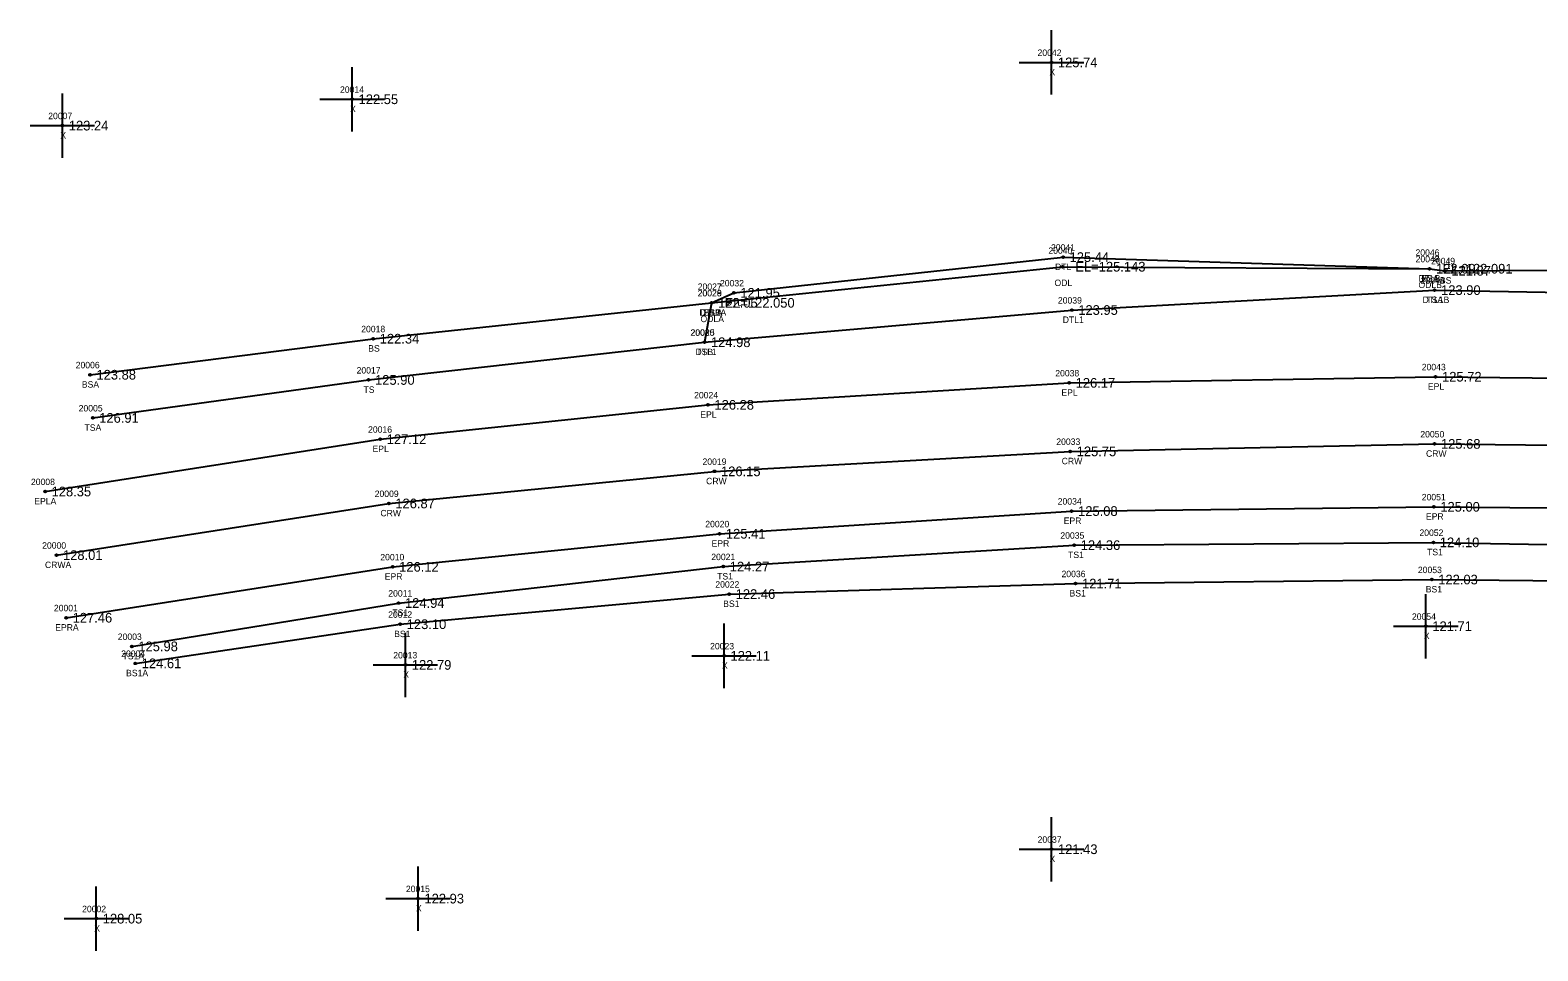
# Model space of a CAD drawing. Extents: x 2375812 to 2377225, y 1024470 to 1025135.
# Drawn here: x 2375812.4 to 2376046.3, y 1024854.8 to 1024997.6 of the extents above; entities that cross this region are included whole.
import ezdxf

# ---------------------------------------------------------------- set-up
doc = ezdxf.new("R2010")
doc.units = 0
for name, color, linetype in [('RD_DTM_BkLn1', 7, 'Continuous'), ('RD_DTM_BkLn2', 7, 'Continuous'), ('RD_DTM_BkLn_txCode', 7, 'Continuous'), ('RD_EX_H2O', 7, 'Continuous'), ('RD_EX_H2O_txCode', 7, 'Continuous'), ('RD_EX_Misc', 7, 'Continuous'), ('RD_EX_Misc_txCode', 7, 'Continuous'), ('RD_EX_Road', 7, 'Continuous'), ('RD_EX_Road_txCode', 7, 'Continuous'), ('RD_EX_TX_H2O_ELEV', 7, 'Continuous'), ('RD_EX_TX_Misc_ELEV', 7, 'Continuous'), ('RD_EX_TX_Road_ELEV', 7, 'Continuous'), ('RD_HC_Survey_ELEV', 7, 'Continuous'), ('RD_HC_Survey_txCode', 7, 'Continuous'), ('RD_SMD_Locator', 7, 'Continuous')]:
    doc.layers.add(name, color=color, linetype=linetype)

msp = doc.modelspace()

# ---------------------------------------------------------------- linework, layer by layer
at = {"layer": 'RD_DTM_BkLn1'}
msp.add_lwpolyline([(2375816.52, 1024916.17), (2375868.08, 1024924.19), (2375918.61, 1024929.17), (2375973.79, 1024932.27), (2376030.31, 1024933.43), (2376124.39, 1024932.38), (2376221.5, 1024931.17), (2376315.07, 1024930.06), (2376410.07, 1024928.46), (2376471.65, 1024927.66)], dxfattribs=at)
at = {"layer": 'RD_DTM_BkLn2'}
for points in [[(2376029.54, 1024960.61), (2376031.93, 1024960.3), (2376124.75, 1024960.87), (2376220.58, 1024959.2), (2376313.51, 1024957.48), (2376410.53, 1024957.56), (2376415.87, 1024960.14)], [(2376030.33, 1024957.29), (2376124.82, 1024955.55), (2376220.6, 1024953.97), (2376313.35, 1024951.76), (2376409.92, 1024949.91), (2376424.84, 1024950.05)], [(2375821.71, 1024944.16), (2375865.66, 1024949.75), (2375918.16, 1024955.32)], [(2375822.14, 1024937.46), (2375864.94, 1024943.35), (2375917.05, 1024949.2)], [(2375828.21, 1024902.01), (2375869.58, 1024908.74), (2375919.97, 1024914.39), (2375974.42, 1024917.72), (2376030.13, 1024918.15), (2376124.55, 1024916.47), (2376157.47, 1024915.82), (2376169.1, 1024907.28), (2376220.97, 1024905.03), (2376312.67, 1024905.48), (2376408.92, 1024907.12), (2376437.56, 1024903.89), (2376467.32, 1024909.88), (2376471.6, 1024914.56)], [(2375828.74, 1024899.38), (2375869.85, 1024905.45), (2375920.89, 1024910.13), (2375974.62, 1024911.75), (2376029.89, 1024912.38), (2376123.86, 1024911.48), (2376128.27, 1024903.93), (2376220.97, 1024899.73), (2376312.35, 1024901.44), (2376410.93, 1024898.57), (2376439.29, 1024896.5), (2376469.35, 1024899.44), (2376491.09, 1024911.59)]]:
    msp.add_lwpolyline(points, dxfattribs=at)
at = {"layer": 'RD_EX_H2O'}
for points in [[(2375918.16, 1024955.32), (2375921.61, 1024956.87), (2375972.69, 1024962.41), (2376029.54, 1024960.61)], [(2375918.16, 1024955.32), (2375972.59, 1024960.92), (2376029.54, 1024960.61)], [(2375918.16, 1024955.32), (2375917.05, 1024949.2), (2375974.04, 1024954.2), (2376030.33, 1024957.29)]]:
    msp.add_lwpolyline(points, dxfattribs=at)
at = {"layer": 'RD_EX_Misc'}
for p, q in [((2375970.88, 1024987.62), (2375970.88, 1024997.62)), ((2375862.38, 1024981.9), (2375862.38, 1024991.9)), ((2375965.88, 1024992.62), (2375975.88, 1024992.62)), ((2375817.42, 1024977.81), (2375817.42, 1024987.81)), ((2375857.38, 1024986.9), (2375867.38, 1024986.9)), ((2375812.42, 1024982.81), (2375822.42, 1024982.81)), ((2376028.97, 1024900.14), (2376028.97, 1024910.14)), ((2375920.08, 1024895.55), (2375920.08, 1024905.55)), ((2376023.97, 1024905.14), (2376033.97, 1024905.14)), ((2375870.64, 1024894.14), (2375870.64, 1024904.14)), ((2375915.08, 1024900.55), (2375925.08, 1024900.55)), ((2375865.64, 1024899.14), (2375875.64, 1024899.14)), ((2375970.89, 1024865.54), (2375970.89, 1024875.54)), ((2375965.89, 1024870.54), (2375975.89, 1024870.54)), ((2375872.6, 1024857.88), (2375872.6, 1024867.88)), ((2375822.69, 1024854.77), (2375822.69, 1024864.77)), ((2375867.6, 1024862.88), (2375877.6, 1024862.88)), ((2375817.69, 1024859.77), (2375827.69, 1024859.77))]:
    msp.add_line(p, q, dxfattribs=at)
at = {"layer": 'RD_EX_Road'}
for points in [[(2375814.75, 1024926.04), (2375866.75, 1024934.16), (2375917.59, 1024939.49), (2375973.63, 1024942.9), (2376030.48, 1024943.85), (2376125.42, 1024942.84), (2376221.25, 1024941.27), (2376314.97, 1024940.08), (2376410.64, 1024938.26), (2376471.87, 1024938.44)], [(2375818.02, 1024906.46), (2375868.67, 1024914.36), (2375919.37, 1024919.49), (2375974.01, 1024923.01), (2376030.21, 1024923.67), (2376124.55, 1024922.83), (2376221.09, 1024921.25), (2376314, 1024920.33), (2376408.92, 1024919.22), (2376471.42, 1024917.38)]]:
    msp.add_lwpolyline(points, dxfattribs=at)
at = {"layer": 'RD_SMD_Locator'}
for centre in [(2375970.88, 1024992.62), (2375862.38, 1024986.9), (2375817.42, 1024982.81), (2375972.59, 1024960.92), (2375972.69, 1024962.41), (2376029.54, 1024960.61), (2376029.54, 1024960.61), (2376029.54, 1024960.61), (2376031.93, 1024960.3), (2375921.61, 1024956.87), (2376030.33, 1024957.29), (2376030.33, 1024957.29), (2375918.16, 1024955.32), (2375918.16, 1024955.32), (2375918.16, 1024955.32), (2375918.16, 1024955.32), (2375974.04, 1024954.2), (2375865.66, 1024949.75), (2375917.05, 1024949.2), (2375917.05, 1024949.2), (2375821.71, 1024944.16), (2375864.94, 1024943.35), (2375973.63, 1024942.9), (2376030.48, 1024943.85), (2375822.14, 1024937.46), (2375917.59, 1024939.49), (2375866.75, 1024934.16), (2376030.31, 1024933.43), (2375973.79, 1024932.27), (2375918.61, 1024929.17), (2375814.75, 1024926.04), (2375868.08, 1024924.19), (2376030.21, 1024923.67), (2375974.01, 1024923.01), (2375919.37, 1024919.49), (2375974.42, 1024917.72), (2376030.13, 1024918.15), (2375816.52, 1024916.17), (2375868.67, 1024914.36), (2375919.97, 1024914.39), (2375974.62, 1024911.75), (2376029.89, 1024912.38), (2375920.89, 1024910.13), (2375869.58, 1024908.74), (2375818.02, 1024906.46), (2375869.85, 1024905.45), (2376028.97, 1024905.14), (2375828.21, 1024902.01), (2375920.08, 1024900.55), (2375828.74, 1024899.38), (2375870.64, 1024899.14), (2375970.89, 1024870.54), (2375872.6, 1024862.88), (2375822.69, 1024859.77)]:
    msp.add_circle(centre, 0.15, dxfattribs=at)

# ---------------------------------------------------------------- texts
at = {"layer": 'RD_DTM_BkLn_txCode'}
for s, p in [('20048', (2376027.38, 1024961.61)), ('20049', (2376029.78, 1024961.3)), ('20045', (2376028.17, 1024958.29)), ('BSA', (2376028.27, 1024958.61)), ('BS', (2376031.15, 1024958.3)), ('20026', (2375915.98, 1024956.32)), ('BSB', (2375916.91, 1024953.32)), ('TSA', (2376029.04, 1024955.29)), ('20018', (2375863.79, 1024950.75)), ('20025', (2375914.9, 1024950.2)), ('BS', (2375864.88, 1024947.75)), ('TSB', (2375915.79, 1024947.2)), ('20006', (2375819.49, 1024945.16)), ('20017', (2375863.07, 1024944.35)), ('BSA', (2375820.44, 1024942.16)), ('TS', (2375864.15, 1024941.35)), ('20005', (2375819.95, 1024938.46)), ('TSA', (2375820.86, 1024935.46)), ('20035', (2375972.26, 1024918.72)), ('20052', (2376027.97, 1024919.15)), ('TS1', (2375973.46, 1024915.72)), ('TS1', (2376029.16, 1024916.15)), ('20021', (2375918.1, 1024915.39)), ('20053', (2376027.73, 1024913.38)), ('20022', (2375918.73, 1024911.13)), ('TS1', (2375919.01, 1024912.39)), ('20036', (2375972.44, 1024912.75)), ('20011', (2375867.99, 1024909.74)), ('BS1', (2375973.68, 1024909.75)), ('BS1', (2376028.95, 1024910.38)), ('20012', (2375867.97, 1024906.45)), ('TS1', (2375868.62, 1024906.74)), ('BS1', (2375919.95, 1024908.13)), ('20003', (2375826.02, 1024903.01)), ('BS1', (2375868.9, 1024903.45)), ('20004', (2375826.55, 1024900.38)), ('TS1A', (2375826.76, 1024900.01)), ('BS1A', (2375827.31, 1024897.38))]:
    msp.add_text(s, height=1, dxfattribs=at).set_placement(p)
at = {"layer": 'RD_EX_H2O_txCode'}
for s, p in [('20040', (2375970.4, 1024962.92)), ('20041', (2375970.81, 1024963.41)), ('20046', (2376027.36, 1024962.61)), ('DTL', (2375971.44, 1024960.41)), ('20047', (2376027.38, 1024961.61)), ('20032', (2375919.45, 1024957.87)), ('ODL', (2375971.35, 1024957.92)), ('DTLB', (2376027.82, 1024958.61)), ('20044', (2376028.17, 1024958.29)), ('20027', (2375916, 1024957.32)), ('20028', (2375916, 1024956.32)), ('20029', (2375916, 1024956.32)), ('ODLB', (2376027.82, 1024957.61)), ('DTL1A', (2375916.26, 1024953.32)), ('DTLA', (2375916.43, 1024953.32)), ('DTL', (2375920.36, 1024954.87)), ('20039', (2375971.88, 1024955.2)), ('DTL1B', (2376028.45, 1024955.29)), ('ODLA', (2375916.43, 1024952.32)), ('DTL1', (2375972.63, 1024952.2)), ('20030', (2375914.86, 1024950.2)), ('DTL1', (2375915.65, 1024947.2))]:
    msp.add_text(s, height=1, dxfattribs=at).set_placement(p)
at = {"layer": 'RD_EX_Misc_txCode'}
for s, p in [('20042', (2375968.72, 1024993.62)), ('X', (2375970.56, 1024990.62)), ('20014', (2375860.5, 1024987.9)), ('20007', (2375815.23, 1024983.81)), ('X', (2375862.06, 1024984.9)), ('X', (2375817.11, 1024980.81)), ('20054', (2376026.81, 1024906.14)), ('20023', (2375917.92, 1024901.55)), ('X', (2376028.65, 1024903.14)), ('20013', (2375868.76, 1024900.14)), ('X', (2375870.32, 1024897.14)), ('X', (2375919.76, 1024898.55)), ('20037', (2375968.73, 1024871.54)), ('X', (2375970.57, 1024868.54)), ('20015', (2375870.72, 1024863.88)), ('20002', (2375820.49, 1024860.77)), ('X', (2375872.28, 1024860.88)), ('X', (2375822.37, 1024857.77))]:
    msp.add_text(s, height=1, dxfattribs=at).set_placement(p)
at = {"layer": 'RD_EX_Road_txCode'}
for s, p in [('20038', (2375971.47, 1024943.9)), ('20043', (2376028.33, 1024944.85)), ('EPL', (2376029.28, 1024941.85)), ('20024', (2375915.44, 1024940.49)), ('EPL', (2375972.42, 1024940.9)), ('EPL', (2375916.39, 1024937.49)), ('20016', (2375864.85, 1024935.16)), ('EPL', (2375865.54, 1024932.16)), ('20008', (2375812.55, 1024927.04)), ('EPLA', (2375813.06, 1024924.04)), ('20034', (2375971.85, 1024924.01)), ('20051', (2376028.33, 1024924.67)), ('20020', (2375917.17, 1024920.49)), ('EPR', (2375972.78, 1024921.01)), ('EPR', (2376028.98, 1024921.67)), ('EPR', (2375918.14, 1024917.49)), ('20010', (2375866.75, 1024915.36)), ('EPR', (2375867.44, 1024912.36)), ('20001', (2375816.11, 1024907.46)), ('EPRA', (2375816.31, 1024904.46))]:
    msp.add_text(s, height=1, dxfattribs=at).set_placement(p)
at = {"layer": 'RD_EX_TX_H2O_ELEV'}
for s, p in [('125.44', (2375973.69, 1024961.66)), ('EL=125.143', (2375974.59, 1024960.17)), ('122.09', (2376030.54, 1024959.86)), ('EL=122.091', (2376031.54, 1024959.86)), ('121.95', (2375922.61, 1024956.12)), ('123.90', (2376031.33, 1024956.54)), ('122.05', (2375919.16, 1024954.57)), ('122.05', (2375919.16, 1024954.57)), ('EL=122.050', (2375920.16, 1024954.57)), ('123.95', (2375975.04, 1024953.45)), ('124.98', (2375918.05, 1024948.45))]:
    msp.add_text(s, height=1.5, dxfattribs=at).set_placement(p)
at = {"layer": 'RD_EX_TX_Misc_ELEV'}
for s, p in [('125.74', (2375971.88, 1024991.87)), ('122.55', (2375863.38, 1024986.15)), ('123.24', (2375818.42, 1024982.06)), ('122.09', (2376030.54, 1024959.86)), ('121.87', (2376032.93, 1024959.55)), ('123.90', (2376031.33, 1024956.54)), ('122.05', (2375919.16, 1024954.57)), ('122.34', (2375866.66, 1024949)), ('124.98', (2375918.05, 1024948.45)), ('123.88', (2375822.71, 1024943.41)), ('125.90', (2375865.94, 1024942.6)), ('126.91', (2375823.14, 1024936.71)), ('124.10', (2376031.13, 1024917.4)), ('124.36', (2375975.42, 1024916.97)), ('124.27', (2375920.97, 1024913.64)), ('121.71', (2375975.62, 1024911)), ('122.03', (2376030.89, 1024911.63)), ('122.46', (2375921.89, 1024909.38)), ('124.94', (2375870.58, 1024907.99)), ('123.10', (2375870.85, 1024904.7)), ('121.71', (2376029.97, 1024904.39)), ('125.98', (2375829.21, 1024901.26)), ('122.11', (2375921.08, 1024899.8)), ('124.61', (2375829.74, 1024898.63)), ('122.79', (2375871.64, 1024898.39)), ('121.43', (2375971.89, 1024869.79)), ('122.93', (2375873.6, 1024862.13)), ('128.05', (2375823.69, 1024859.02))]:
    msp.add_text(s, height=1.5, dxfattribs=at).set_placement(p)
at = {"layer": 'RD_EX_TX_Road_ELEV'}
for s, p in [('125.72', (2376031.48, 1024943.1)), ('126.17', (2375974.63, 1024942.15)), ('126.28', (2375918.59, 1024938.74)), ('127.12', (2375867.75, 1024933.41)), ('128.35', (2375815.75, 1024925.29)), ('125.08', (2375975.01, 1024922.26)), ('125.00', (2376031.21, 1024922.92)), ('125.41', (2375920.37, 1024918.74)), ('126.12', (2375869.67, 1024913.61)), ('127.46', (2375819.02, 1024905.71))]:
    msp.add_text(s, height=1.5, dxfattribs=at).set_placement(p)
at = {"layer": 'RD_HC_Survey_ELEV'}
for s, p in [('125.75', (2375974.79, 1024931.52)), ('125.68', (2376031.31, 1024932.68)), ('126.15', (2375919.61, 1024928.42)), ('126.87', (2375869.08, 1024923.44)), ('128.01', (2375817.52, 1024915.42))]:
    msp.add_text(s, height=1.5, dxfattribs=at).set_placement(p)
at = {"layer": 'RD_HC_Survey_txCode'}
for s, p in [('20050', (2376028.11, 1024934.43)), ('20033', (2375971.63, 1024933.27)), ('20019', (2375916.74, 1024930.17)), ('CRW', (2375972.47, 1024930.27)), ('CRW', (2376028.99, 1024931.43)), ('20009', (2375865.88, 1024925.19)), ('CRW', (2375917.3, 1024927.17)), ('CRW', (2375866.77, 1024922.19)), ('20000', (2375814.29, 1024917.17)), ('CRWA', (2375814.72, 1024914.17))]:
    msp.add_text(s, height=1, dxfattribs=at).set_placement(p)

doc.saveas('drawing.dxf')
